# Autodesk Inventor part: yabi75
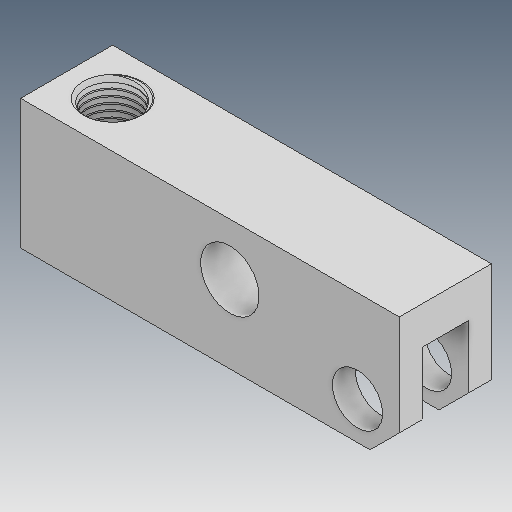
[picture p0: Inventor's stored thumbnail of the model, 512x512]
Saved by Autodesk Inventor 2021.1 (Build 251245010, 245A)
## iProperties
Created: 2018-07
Part Number: yabi75
Material: Ogólny
Document SubType Name: Modeling
Designer: user
Density: 1 g/cm^3
Appearance: Domyślna
Author: user
Revision Number: ÈÎºÎ
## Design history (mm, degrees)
feature "ÇÐ³ý-À­Éì2"
node "Bryła1"
